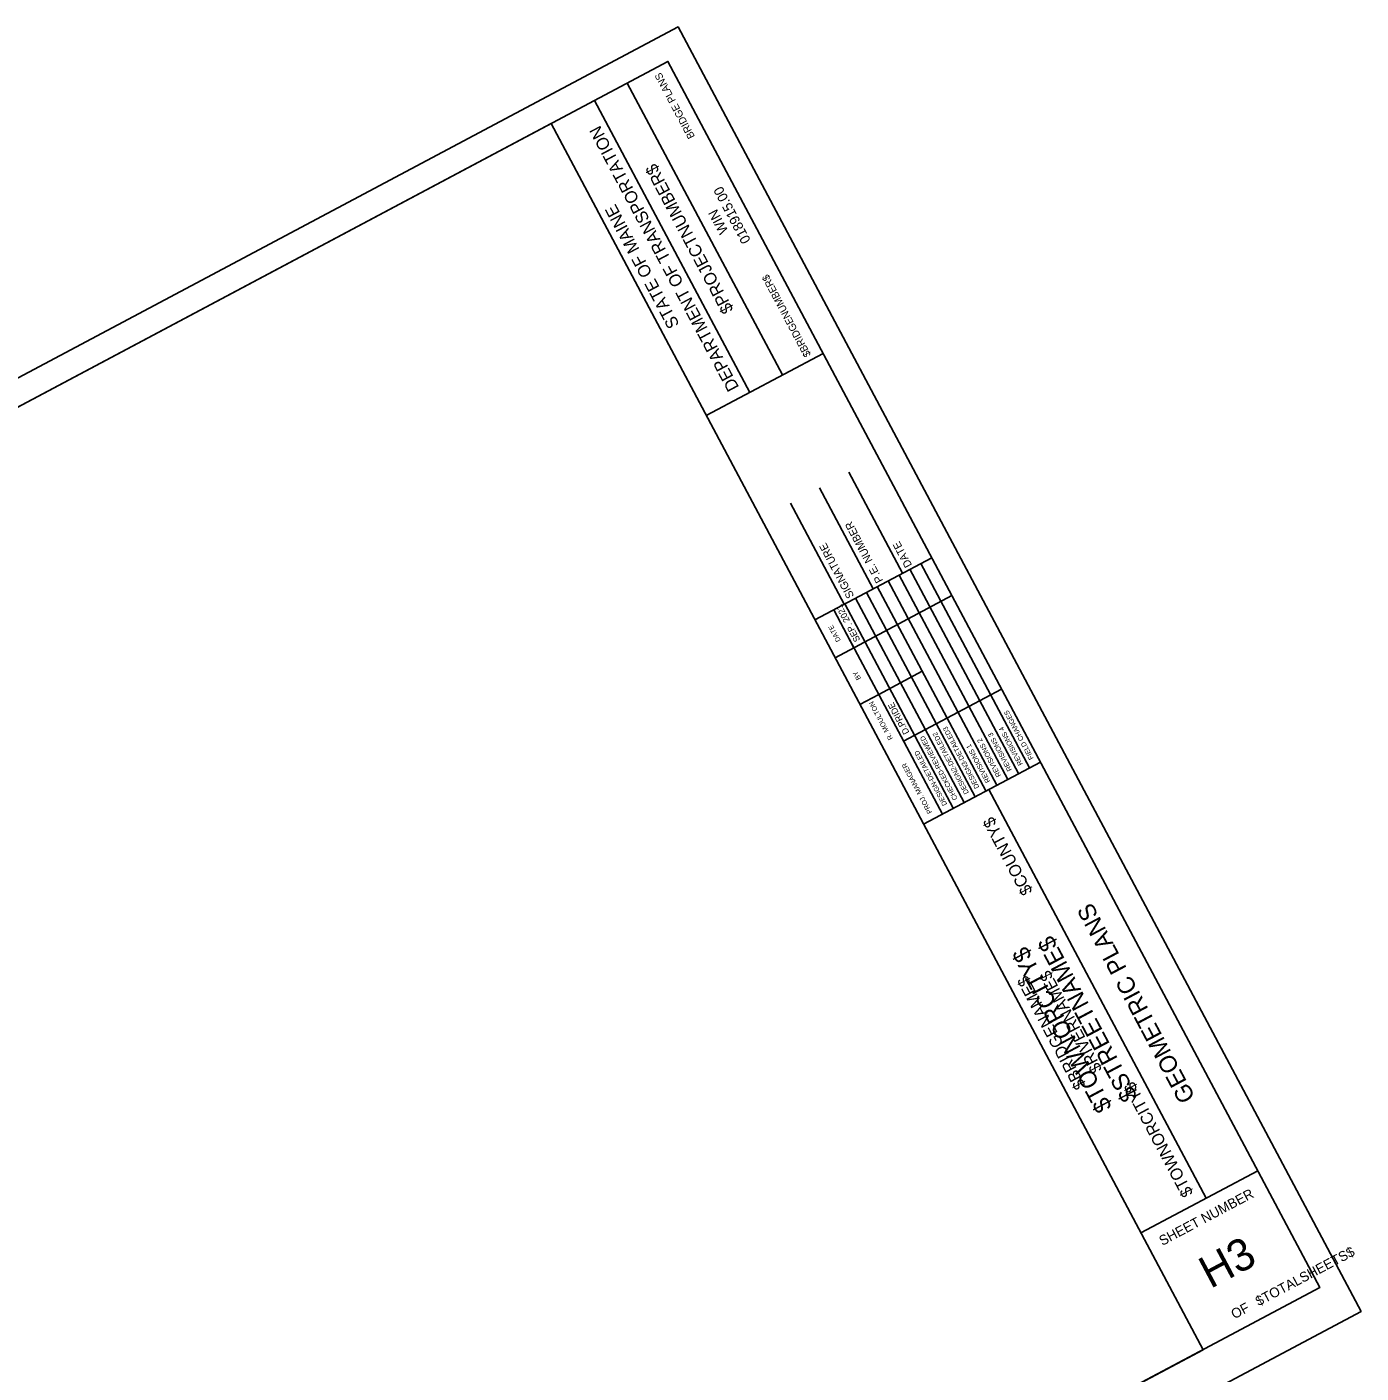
# Model space of a CAD drawing. Extents: x 1743286 to 1744295, y 462273 to 463157.
# Drawn here: x 1743790 to 1744295, y 462648 to 463157 of the extents above; entities that cross this region are included whole.
import ezdxf

# ---------------------------------------------------------------- set-up
doc = ezdxf.new("R2010")
doc.units = 0
for name, color, linetype in [('ANNOTATION', 7, 'Continuous'), ('D_Roadway_Centerline_Flags', 7, 'Continuous'), ('DIMENSIONS', 7, 'Continuous'), ('M_Fencing', 7, 'Continuous'), ('M_Misc_MiscItems', 7, 'Continuous')]:
    doc.layers.add(name, color=color, linetype=linetype)

msp = doc.modelspace()

# ---------------------------------------------------------------- linework, layer by layer
at = {"layer": 'DIMENSIONS'}
for p, q in [((1744075.92, 463025.68), (1744017.24, 463136.05)), ((1744063.58, 463019.12), (1744004.9, 463129.49)), ((1744234.9, 462657.2), (1743988.43, 463120.75)), ((1744047.13, 463010.36), (1744091.27, 463033.83)), ((1744121.3, 462950.74), (1744101, 462988.92)), ((1744110.26, 462944.87), (1744089.96, 462983.05)), ((1744099.22, 462939), (1744078.92, 462977.18)), ((1744088.18, 462933.14), (1744132.33, 462956.61)), ((1744129.26, 462855.88), (1744173.41, 462879.35)), ((1744236.1, 462714.49), (1744153.95, 462869)), ((1744211.42, 462701.36), (1744255.57, 462724.84))]:
    msp.add_line(p, q, dxfattribs=at)
msp.add_lwpolyline([(1743326.22, 462768.65), (1744032.58, 463144.22), (1744279.05, 462680.68), (1743572.69, 462305.1)], close=True, dxfattribs=at)
for points in [[(1744165.18, 462874.99), (1744124.11, 462952.24)], [(1744169.29, 462877.18), (1744128.22, 462954.42)], [(1744156.96, 462870.62), (1744115.88, 462947.86)], [(1744161.07, 462872.81), (1744120, 462950.05)], [(1744095.81, 462918.79), (1744139.96, 462942.26)], [(1744148.73, 462866.24), (1744107.66, 462943.49)], [(1744152.84, 462868.43), (1744111.77, 462945.68)], [(1744102.94, 462922.58), (1744095.31, 462936.93)], [(1744140.5, 462861.87), (1744099.43, 462939.12)], [(1744103.54, 462941.3), (1744144.62, 462864.06)], [(1744136.39, 462859.68), (1744096.98, 462933.81)], [(1744112.33, 462904.92), (1744128.78, 462913.67)], [(1744121.72, 462887.26), (1744158.74, 462906.94)], [(1744105.2, 462901.13), (1744112.34, 462904.92)]]:
    msp.add_lwpolyline(points, dxfattribs=at)
at = {"layer": 'M_Fencing'}
msp.add_lwpolyline([(1743544.14, 462272.59), (1744294.65, 462671.65), (1744036.44, 463157.27), (1743285.93, 462758.22)], close=True, dxfattribs=at)
at = {"layer": 'M_Misc_MiscItems'}
msp.add_lwpolyline([(1743326.22, 462768.65), (1743988.43, 463120.75), (1744234.9, 462657.2), (1743572.69, 462305.1)], close=True, dxfattribs=at)

# ---------------------------------------------------------------- texts
at = {"layer": 'ANNOTATION'}
for s, height, p in [('BRIDGE PLANS', 2.795, (1744042.89, 463115.87)), ('$BRIDGENUMBER$', 2.795, (1744086.77, 463033.34)), ('$COUNTY$', 4.536, (1744170.63, 462830.48)), ('$RIVERNAME$', 4.5358, (1744196.91, 462763.2)), ('$BRIDGENAME$', 4.5358, (1744190.71, 462756.99)), ('$TOWNORCITY$', 4.5358, (1744231.33, 462716.33))]:
    msp.add_text(s, height=height, rotation=118, dxfattribs=at).set_placement(p)
at = {"layer": 'D_Roadway_Centerline_Flags'}
for s, p in [('$TOWNORCITY$', (1744200.69, 462748.94)), ('$STREETNAME$', (1744210.33, 462753.04))]:
    msp.add_text(s, height=6.5214, rotation=118, dxfattribs=at).set_placement(p)
at = {"layer": 'DIMENSIONS'}
for s, height, rotation, p in [('DEPARTMENT OF TRANSPORTATION', 4.6588, 118, (1744059.61, 463021.02)), ('$PROJECTNUMBER$', 4.6588, 118, (1744057.53, 463050.34)), ('018915.00', 3.726, 118, (1744064.01, 463076.55)), ('STATE OF MAINE', 4.6588, 118, (1744037.08, 463044.75)), ('WIN', 3.726, 118, (1744055.53, 463080.15)), ('P.E. NUMBER', 2.9528, 118, (1744114.05, 462947.98)), ('SIGNATURE', 2.953, 118, (1744103.1, 462942.15)), ('DATE', 2.953, 118, (1744125, 462953.8)), ('SEP. 2021', 2.423, 118, (1744105.38, 462925.55)), ('DATE', 1.857, 118, (1744098, 462925.36)), ('BY', 1.857, 118, (1744105.68, 462910.93)), ('R. MOULTON', 1.864, 118, (1744117.73, 462888.27)), ('D.PRIDE', 2.423, 118, (1744123.97, 462890.57)), ('FIELD CHANGES', 1.8637, 118, (1744170.95, 462880.81)), ('DESIGN3-DETAILED3', 1.8637, 118, (1744150.39, 462869.87)), ('REVISIONS 4', 1.8637, 118, (1744166.84, 462878.62)), ('CHECKED-REVIEWED', 1.8637, 118, (1744142.16, 462865.5)), ('DESIGN2-DETAILED2', 1.8637, 118, (1744146.44, 462867.77)), ('REVISIONS 2', 1.8637, 118, (1744158.61, 462874.25)), ('REVISIONS 3', 1.8637, 118, (1744162.73, 462876.43)), ('DESIGN-DETAILED', 1.8637, 118, (1744138.21, 462863.4)), ('REVISIONS 1', 1.8637, 118, (1744154.5, 462872.06)), ('PROJ. MANAGER', 1.8637, 118, (1744132.55, 462860.39)), ('GEOMETRIC PLANS', 6.5214, 118, (1744232.12, 462752.58)), ('SHEET NUMBER', 3.7264, 28, (1744219.52, 462696.4)), ('H3', 12.097, 28, (1744237.69, 462680.1)), ('$TOTALSHEETS$', 3.7264, 28, (1744255.96, 462673.57)), ('OF', 3.726, 28, (1744246.74, 462668.67))]:
    msp.add_text(s, height=height, rotation=rotation, dxfattribs=at).set_placement(p)

doc.saveas('drawing.dxf')
